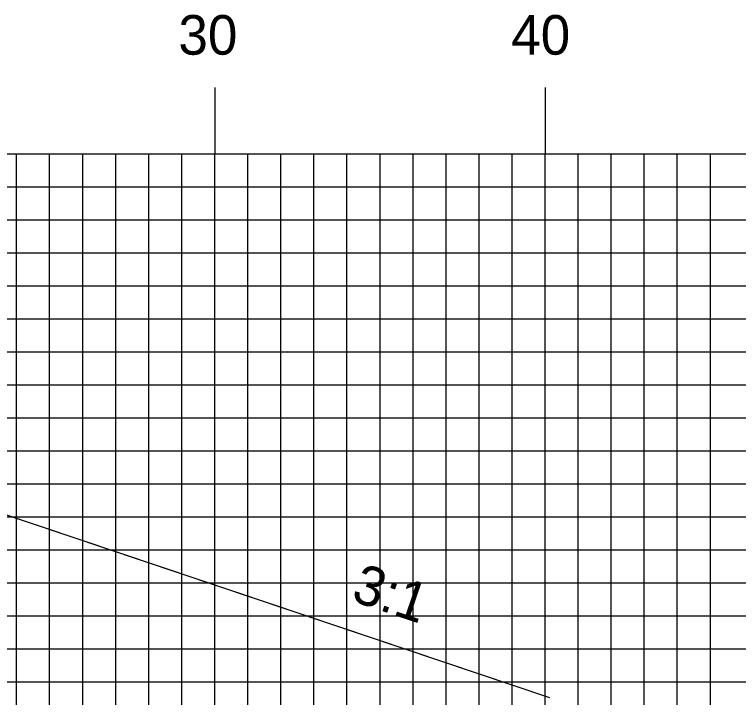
# Model space of a CAD drawing. Extents: x 856323 to 856666, y 364765 to 364985.
# Drawn here: x 856512.7 to 856534.62, y 364836.83 to 364857.52 of the extents above; entities that cross this region are included whole.
import ezdxf

# ---------------------------------------------------------------- set-up
doc = ezdxf.new("R2010")
doc.units = 0
for name, color, linetype in [('ANNOTATION', 7, 'Continuous'), ('D_Roadway_Centerline', 7, 'Continuous'), ('D_Roadway_SlopeLines', 7, 'Continuous'), ('H_V ANNOTATION', 7, 'Continuous'), ('MAJOR', 7, 'Continuous'), ('MINOR', 7, 'Continuous')]:
    doc.layers.add(name, color=color, linetype=linetype)

msp = doc.modelspace()

# ---------------------------------------------------------------- linework, layer by layer
at = {"layer": 'D_Roadway_Centerline'}
msp.add_lwpolyline([(856476.17, 364847.458), (856483.623, 364847.116), (856488.768, 364846.88), (856491.27, 364846.765), (856496.768, 364846.512), (856500.528, 364845.572), (856508.768, 364843.512), (856509.507, 364843.328), (856509.84, 364843.244), (856518.287, 364840.401), (856528.903, 364836.827)], dxfattribs=at)
at = {"layer": 'D_Roadway_SlopeLines'}
msp.add_lwpolyline([(856496.768, 364846.512), (856509.84, 364843.244), (856528.902, 364836.827)], dxfattribs=at)
at = {"layer": 'MAJOR'}
for p, q in [((856518.768, 364855.306), (856518.768, 364853.302)), ((856528.768, 364855.306), (856528.768, 364853.302)), ((856348.768, 364853.302), (856628.768, 364853.302)), ((856348.768, 364853.302), (856628.768, 364853.302)), ((856518.768, 364828.302), (856518.768, 364853.302)), ((856528.768, 364828.302), (856528.768, 364853.302)), ((856348.768, 364848.302), (856628.768, 364848.302)), ((856348.768, 364843.302), (856628.768, 364843.302)), ((856348.768, 364838.302), (856628.768, 364838.302))]:
    msp.add_line(p, q, dxfattribs=at)
at = {"layer": 'MINOR'}
for p, q in [((856512.768, 364828.302), (856512.768, 364853.302)), ((856513.768, 364828.302), (856513.768, 364853.302)), ((856514.768, 364828.302), (856514.768, 364853.302)), ((856515.768, 364828.302), (856515.768, 364853.302)), ((856516.768, 364828.302), (856516.768, 364853.302)), ((856517.768, 364828.302), (856517.768, 364853.302)), ((856519.768, 364828.302), (856519.768, 364853.302)), ((856520.768, 364828.302), (856520.768, 364853.302)), ((856521.768, 364828.302), (856521.768, 364853.302)), ((856522.768, 364828.302), (856522.768, 364853.302)), ((856523.768, 364828.302), (856523.768, 364853.302)), ((856524.768, 364828.302), (856524.768, 364853.302)), ((856525.768, 364828.302), (856525.768, 364853.302)), ((856526.768, 364828.302), (856526.768, 364853.302)), ((856527.768, 364828.302), (856527.768, 364853.302)), ((856529.768, 364828.302), (856529.768, 364853.302)), ((856530.768, 364828.302), (856530.768, 364853.302)), ((856531.768, 364828.302), (856531.768, 364853.302)), ((856532.768, 364828.302), (856532.768, 364853.302)), ((856533.768, 364828.302), (856533.768, 364853.302)), ((856348.768, 364852.302), (856628.768, 364852.302)), ((856348.768, 364851.302), (856628.768, 364851.302)), ((856348.768, 364850.302), (856628.768, 364850.302)), ((856348.768, 364849.302), (856628.768, 364849.302)), ((856348.768, 364847.302), (856628.768, 364847.302)), ((856348.768, 364846.302), (856628.768, 364846.302)), ((856348.768, 364845.302), (856628.768, 364845.302)), ((856348.768, 364844.302), (856628.768, 364844.302)), ((856348.768, 364842.302), (856628.768, 364842.302)), ((856348.768, 364841.302), (856628.768, 364841.302)), ((856348.768, 364840.302), (856628.768, 364840.302)), ((856348.768, 364839.302), (856628.768, 364839.302)), ((856348.768, 364837.302), (856628.768, 364837.302))]:
    msp.add_line(p, q, dxfattribs=at)

# ---------------------------------------------------------------- texts
at = {"layer": 'ANNOTATION'}
msp.add_text('3:1', height=1.2, rotation=341.3936, dxfattribs=at).set_placement((856522.856, 364839.773))
at = {"layer": 'H_V ANNOTATION'}
for s, p in [('30', (856517.666, 364856.302)), ('40', (856527.741, 364856.302))]:
    msp.add_text(s, height=1.2, dxfattribs=at).set_placement(p)

doc.saveas('drawing.dxf')
